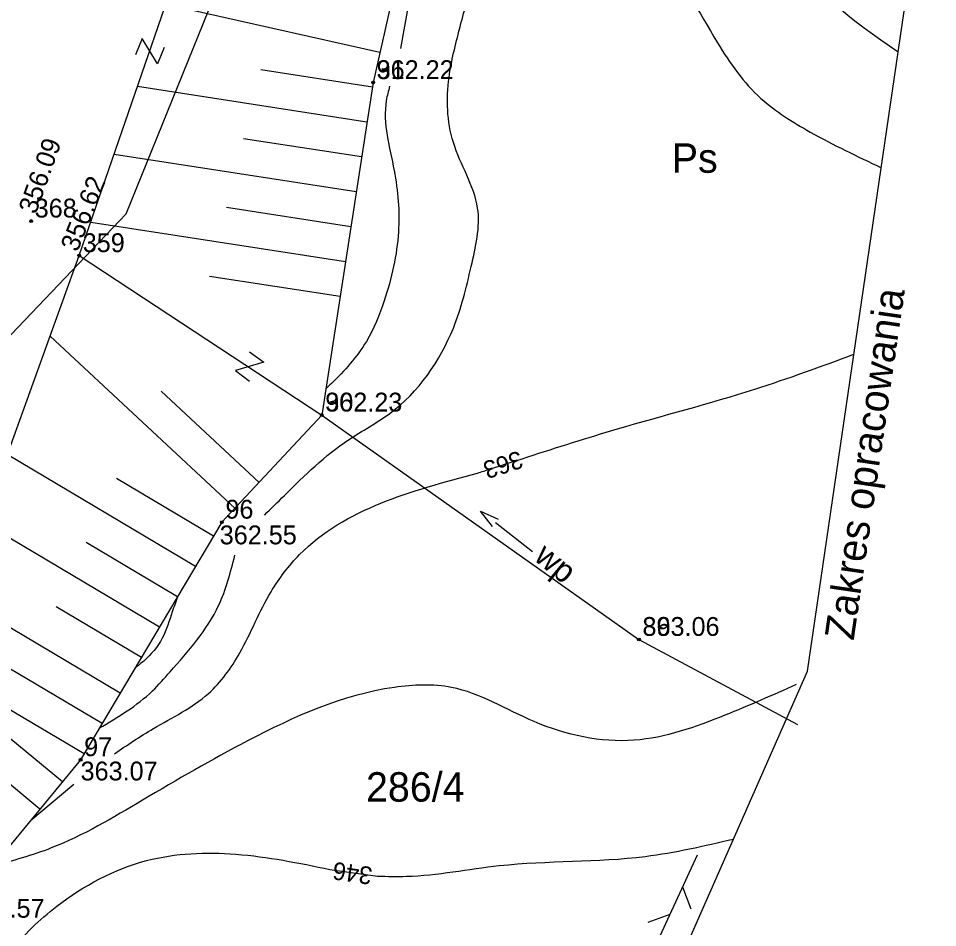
# Model space of a CAD drawing. Extents: x 4635329 to 4651863, y 5356628 to 5367582.
# Drawn here: x 4651757.46 to 4651796.49, y 5357115.3 to 5357153.92 of the extents above; entities that cross this region are included whole.
import ezdxf

# ---------------------------------------------------------------- set-up
doc = ezdxf.new("R2010")
doc.units = 0
for name, color, linetype in [('Level 1', 7, 'Continuous'), ('Level 12', 7, 'Continuous'), ('Level 32', 7, 'Continuous'), ('Level 4', 7, 'Continuous'), ('Level 44', 7, 'Continuous'), ('Level 45', 7, 'Continuous'), ('Level 46', 7, 'Continuous'), ('Level 47', 7, 'Continuous'), ('Level 48', 7, 'Continuous'), ('Level 5', 7, 'Continuous'), ('Level 50', 7, 'Continuous'), ('Level 51', 7, 'Continuous'), ('Level 53', 7, 'Continuous'), ('Level 6', 7, 'Continuous'), ('Level 63', 7, 'Continuous')]:
    doc.layers.add(name, color=color, linetype=linetype)

msp = doc.modelspace()

# ---------------------------------------------------------------- linework, layer by layer
at = {"layer": 'Level 1'}
for p, q in [((4651790.97, 5357126.195), (4651801.01, 5357194.891)), ((4651782.36, 5357106.665), (4651790.97, 5357126.195))]:
    msp.add_line(p, q, dxfattribs=at)
at = {"layer": 'Level 32'}
for p, q in [((4651784.199, 5357113.854), (4651786.294, 5357118.394)), ((4651785.665, 5357117.032), (4651786.011, 5357116.094)), ((4651785.124, 5357115.858), (4651784.186, 5357115.512))]:
    msp.add_line(p, q, dxfattribs=at)
at = {"layer": 'Level 4'}
for p, q in [((4651762.032, 5357145.618), (4651773.552, 5357174.065)), ((4651745.963, 5357128.756), (4651762.032, 5357145.618))]:
    msp.add_line(p, q, dxfattribs=at)
at = {"layer": 'Level 44'}
for centre in [(4651772.52, 5357151.19), (4651758, 5357145.31), (4651760.04, 5357143.84), (4651770.34, 5357137.07), (4651766.1, 5357132.52), (4651783.81, 5357127.54), (4651760.1, 5357122.43)]:
    msp.add_circle(centre, 0.04, dxfattribs=at)
at = {"layer": 'Level 46'}
for p, q in [((4651757.97, 5357119.848), (4651759.811, 5357121.395)), ((4651770.685, 5357117.772), (4651772.712, 5357117.486))]:
    msp.add_line(p, q, dxfattribs=at)
for points in [[(4651794.813, 5357152.488), (4651790.386, 5357157.128), (4651790.053, 5357160.494), (4651787.87, 5357165.517)], [(4651775.778, 5357159.098), (4651774.955, 5357157.543), (4651773.682, 5357152.641)], [(4651767.905, 5357132.82), (4651768.751, 5357133.654), (4651771.479, 5357136.02), (4651773.238, 5357137.142), (4651775.928, 5357140.766), (4651776.686, 5357143.374), (4651776.959, 5357145.861), (4651775.928, 5357148.651), (4651775.746, 5357151.41), (4651776.201, 5357153.503), (4651776.895, 5357155.4), (4651784.353, 5357156.461), (4651787.142, 5357152.883), (4651788.991, 5357150.517), (4651791.083, 5357149.092), (4651794.095, 5357147.575)], [(4651773.222, 5357151.034), (4651773.082, 5357150.432), (4651773.415, 5357147.46), (4651773.597, 5357144.852), (4651772.992, 5357141.928), (4651772.234, 5357140.2), (4651770.749, 5357138.41), (4651770.512, 5357138.186)], [(4651779.086, 5357135.292), (4651782.892, 5357136.48), (4651788.725, 5357138.167), (4651792.937, 5357139.653)], [(4651776.952, 5357134.604), (4651777.222, 5357134.691), (4651779.086, 5357135.292)], [(4651761.532, 5357122.683), (4651763.19, 5357123.753), (4651765.525, 5357125.239), (4651766.859, 5357126.968), (4651768.188, 5357129.565), (4651769.401, 5357131.142), (4651776.952, 5357134.604)], [(4651760.893, 5357123.764), (4651763.147, 5357125.352), (4651763.9, 5357126.164), (4651765.962, 5357128.984), (4651766.65, 5357131.114)], [(4651764.235, 5357129.383), (4651763.992, 5357128.713), (4651763.568, 5357127.591), (4651762.78, 5357126.621), (4651762.422, 5357126.334)], [(4651790.492, 5357125.623), (4651787.46, 5357124.319), (4651783.61, 5357123.258), (4651779.365, 5357124.047), (4651775.849, 5357125.502), (4651773.423, 5357125.502), (4651767.19, 5357123.23), (4651762.733, 5357120.713), (4651758.853, 5357118.681), (4651756.364, 5357117.902)], [(4651772.712, 5357117.486), (4651773.939, 5357117.479), (4651777.88, 5357117.933), (4651784.078, 5357118.326), (4651787.826, 5357119.063)], [(4651754.793, 5357102.394), (4651755.147, 5357104.754), (4651755.905, 5357108.242), (4651755.935, 5357111.456), (4651757.114, 5357114.234), (4651759.084, 5357116.205), (4651762.904, 5357118.146), (4651766.694, 5357118.419), (4651770.685, 5357117.772)]]:
    msp.add_spline(points, degree=3, dxfattribs=at)
at = {"layer": 'Level 48'}
for p, q in [((4651772.807, 5357152.463), (4651763.714, 5357154.513)), ((4651772.49, 5357150.997), (4651767.749, 5357151.729)), ((4651772.261, 5357149.515), (4651762.512, 5357151.02)), ((4651772.032, 5357148.032), (4651767.024, 5357148.806)), ((4651771.804, 5357146.55), (4651761.519, 5357148.138)), ((4651771.575, 5357145.067), (4651766.299, 5357145.882)), ((4651771.346, 5357143.585), (4651760.527, 5357145.255)), ((4651771.117, 5357142.103), (4651765.574, 5357142.958)), ((4651766.653, 5357133.114), (4651758.806, 5357140.426)), ((4651767.676, 5357134.211), (4651763.518, 5357138.086)), ((4651764.981, 5357130.639), (4651756.987, 5357135.393)), ((4651765.748, 5357131.928), (4651761.627, 5357134.379)), ((4651763.448, 5357128.06), (4651755.949, 5357132.52)), ((4651764.215, 5357129.35), (4651760.341, 5357131.653)), ((4651761.78, 5357125.255), (4651754.483, 5357129.594)), ((4651762.681, 5357126.771), (4651759.056, 5357128.927)), ((4651760.247, 5357122.676), (4651751.71, 5357127.753)), ((4651758.373, 5357120.337), (4651750.422, 5357126.898)), ((4651761.013, 5357123.966), (4651757.055, 5357126.32)), ((4651759.328, 5357121.494), (4651755.528, 5357124.63))]:
    msp.add_line(p, q, dxfattribs=at)
msp.add_lwpolyline([(4651788.23, 5357177.15), (4651778.95, 5357165), (4651774.56, 5357160.24), (4651772.52, 5357151.19), (4651770.34, 5357137.07), (4651766.1, 5357132.52), (4651760.1, 5357122.43), (4651755.24, 5357116.54), (4651754.43, 5357111.05), (4651754.06, 5357101.72), (4651764.92, 5357096.97)], dxfattribs=at)
at = {"layer": 'Level 50'}
for p, q in [((4651760.04, 5357143.84), (4651767.53, 5357165.6)), ((4651755.02, 5357129.95), (4651760.04, 5357143.84)), ((4651760.04, 5357143.84), (4651770.34, 5357137.07)), ((4651770.34, 5357137.07), (4651783.81, 5357127.54)), ((4651777.59, 5357132.334), (4651777.083, 5357132.984)), ((4651777.083, 5357132.984), (4651777.837, 5357132.648)), ((4651779.288, 5357131.258), (4651777.713, 5357132.491)), ((4651783.81, 5357127.54), (4651790.539, 5357123.931))]:
    msp.add_line(p, q, dxfattribs=at)
at = {"layer": 'Level 53'}
for p, q in [((4651762.719, 5357153.061), (4651762.434, 5357152.368)), ((4651763.359, 5357151.988), (4651762.719, 5357153.061)), ((4651763.644, 5357152.681), (4651763.359, 5357151.988)), ((4651767.274, 5357139.761), (4651767.874, 5357139.31)), ((4651767.874, 5357139.31), (4651766.674, 5357138.961)), ((4651766.674, 5357138.961), (4651767.274, 5357138.51))]:
    msp.add_line(p, q, dxfattribs=at)
at = {"layer": 'Level 63'}
for centre in [(4651772.52, 5357151.19), (4651758, 5357145.31), (4651760.04, 5357143.84), (4651770.34, 5357137.07), (4651766.1, 5357132.52), (4651783.81, 5357127.54), (4651760.1, 5357122.43)]:
    msp.add_circle(centre, 0.06, dxfattribs=at)

# ---------------------------------------------------------------- texts
at = {"layer": 'Level 12'}
msp.add_text('Ps', height=1.25, dxfattribs=at).set_placement((4651785.204, 5357147.361))
at = {"layer": 'Level 45'}
for s, p in [('362.22', (4651772.67, 5357151.34)), ('362.23', (4651770.49, 5357137.22)), ('362.55', (4651766.007, 5357131.579)), ('363.06', (4651783.96, 5357127.69)), ('363.07', (4651760.098, 5357121.55)), ('363.57', (4651755.299, 5357115.72))]:
    msp.add_text(s, height=0.8, dxfattribs=at).set_placement(p)
for s, rotation, p in [('356.09', 70.3721, (4651758.196, 5357145.564)), ('356.62', 68.2961, (4651759.965, 5357143.965))]:
    msp.add_text(s, height=0.8, rotation=rotation, dxfattribs=at).set_placement(p)
at = {"layer": 'Level 47'}
for s, rotation, p in [('363', 197.9013, (4651778.724, 5357135.57)), ('346', 171.673, (4651772.527, 5357117.856))]:
    msp.add_text(s, height=0.75, rotation=rotation, dxfattribs=at).set_placement(p)
at = {"layer": 'Level 5'}
msp.add_text('286/4', height=1.25, dxfattribs=at).set_placement((4651772.22, 5357120.65))
at = {"layer": 'Level 51'}
msp.add_text('wp', height=1, rotation=320.5701, dxfattribs=at).set_placement((4651779.302, 5357130.944))
at = {"layer": 'Level 6'}
msp.add_text('Zakres opracowania', height=1.25, rotation=81.685, dxfattribs=at).set_placement((4651792.925, 5357127.468))
at = {"layer": 'Level 63'}
for s, p in [('91', (4651772.67, 5357151.34)), ('368', (4651758.15, 5357145.46)), ('359', (4651760.19, 5357143.99)), ('90', (4651770.49, 5357137.22)), ('96', (4651766.25, 5357132.67)), ('89', (4651783.96, 5357127.69)), ('97', (4651760.25, 5357122.58))]:
    msp.add_text(s, height=0.8, dxfattribs=at).set_placement(p)

doc.saveas('drawing.dxf')
